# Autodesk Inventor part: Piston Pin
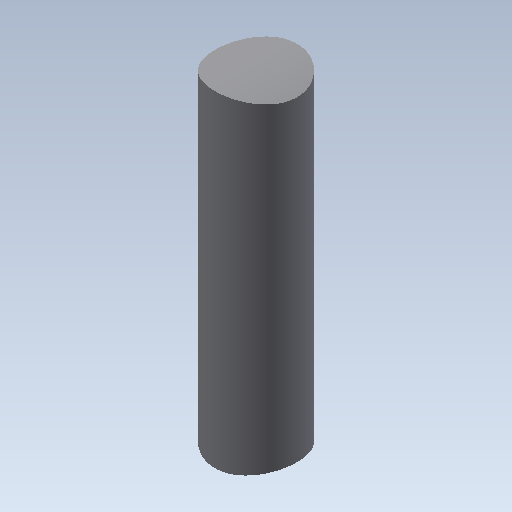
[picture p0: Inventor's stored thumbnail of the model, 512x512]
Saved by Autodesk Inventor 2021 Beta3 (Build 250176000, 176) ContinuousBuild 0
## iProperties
Created: 2012-08
Part Number: Piston Pin
Material: Generic
Document SubType Name: Modeling
Designer: John
Density: 1 g/cm^3
Appearance: Default
Author: John
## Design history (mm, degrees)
sketch "Sketch1"
  geometry: C1 r 1.74 at (0, 0); 1 further point
  constraints: 1 centre point, 1 coincident
  dimensions: "d0" = 3.4798 diameter of C1
extrude "Extrusion1" new body sketch "Sketch1" stored distance "d1" = 13.843; taper "d2" = 0 deg
sketch "Sketch2"
  geometry: L1 (-1.74, -6.921)-(1.74, -6.921) reference; L2 (1.74, 6.921)-(-1.74, 6.921) reference; L3 (0, 6.921)-(0, -6.921); 3 further points
  constraints: 2 coincident, 2 end point, 2 midpoint, 1 vertical alignment, 5 other
extrude "Extrusion2" cut sketch "Sketch2" extent not by distance; stored distance "d3" = 25.4; taper "d4" = 0 deg
body "Solid1"
node "Projected Loop1"
node "Projected Loop2"
